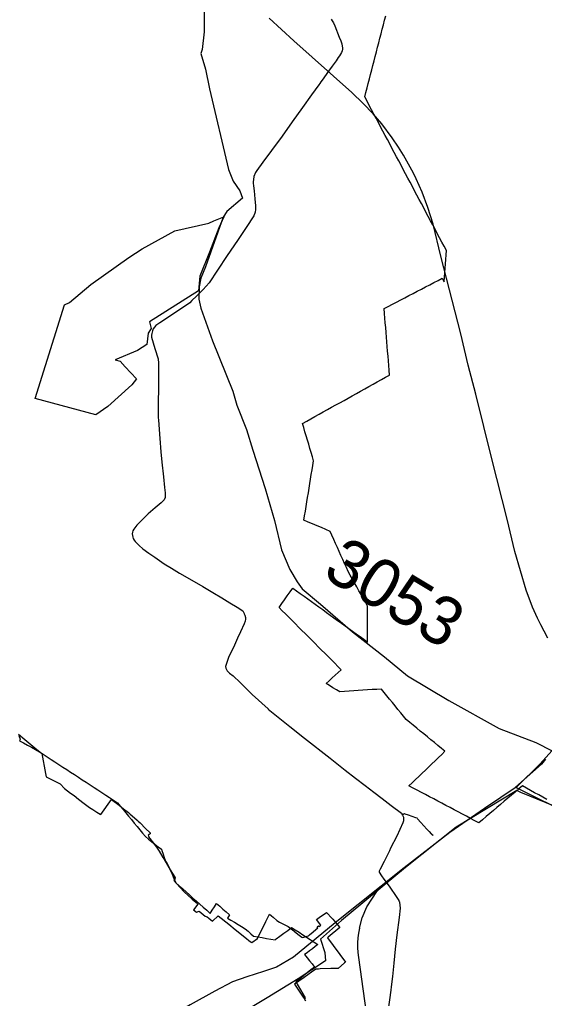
# Model space of a CAD drawing. Extents: x -789162 to -606354, y -1062736 to -945481.
# Drawn here: x -723737 to -722652, y -987074 to -985051 of the extents above; entities that cross this region are included whole.
import ezdxf

# ---------------------------------------------------------------- set-up
doc = ezdxf.new("R2010")
doc.units = 0
for name, color, linetype in [('_SIRSI VZTAHY CHKO HRANICE', 7, 'Continuous'), ('_SIRSI VZTAHY_CYKLOTRASY MISTNI S', 7, 'Continuous'), ('_SIRSI VZTAHY_CYKLOTRASY MISTNI_POPIS', 7, 'Continuous'), ('_SIRSI VZTAHY_NATURA_EVL', 7, 'Continuous'), ('_SIRSI VZTAHY_OP vodnich zdroju II stupne', 7, 'Continuous'), ('_SIRSI VZTAHY_SILNICE III TRIDY_NAVRH', 7, 'Continuous'), ('_SIRSI VZTAHY_SILNICE III TRIDY_STAV', 7, 'Continuous'), ('_SIRSI VZTAHY_VTL PLYNOVOD', 7, 'Continuous'), ('_SIRSI VZTAHY_ZELEZNICE STAV', 7, 'Continuous')]:
    doc.layers.add(name, color=color, linetype=linetype)

msp = doc.modelspace()

# ---------------------------------------------------------------- linework, layer by layer
at = {"layer": '_SIRSI VZTAHY CHKO HRANICE'}
msp.add_lwpolyline([(-723739.4, -986527.5), (-723726.3, -986538.3), (-723713.9, -986549.2), (-723705.7, -986555.6), (-723695.8, -986564.1), (-723691.6, -986567.8), (-723683.6, -986608.7), (-723682.2, -986615.9), (-723653.4, -986630.5), (-723644.2, -986640), (-723631.9, -986649.4), (-723624.9, -986654.7), (-723615.4, -986662), (-723604, -986670.7), (-723592.6, -986679.4), (-723585.9, -986683.5), (-723577.7, -986688.6), (-723570.8, -986692.8), (-723569.2, -986693.4), (-723547.2, -986662.3), (-723531.8, -986674.6), (-723522.4, -986682.1), (-723512.1, -986689.8), (-723508.5, -986693), (-723504.7, -986696.6), (-723494.5, -986705.6), (-723492.4, -986707.5), (-723488.4, -986711.2), (-723477.2, -986722.3), (-723467.3, -986731.7), (-723467.3, -986733.3), (-723471.5, -986736.4), (-723470.2, -986738.9), (-723470.7, -986739.7), (-723460.7, -986753.2), (-723453, -986763.4), (-723448.6, -986769.6), (-723441.4, -986782.3), (-723439.5, -986785.6), (-723431.4, -986798.7), (-723426, -986807.9), (-723420.2, -986817.8), (-723415.9, -986824.7), (-723416.9, -986829.3), (-723418.4, -986830.4), (-723413.3, -986836.3), (-723398.1, -986852.6), (-723395.9, -986854.9), (-723389.5, -986860.7), (-723380.4, -986868.4), (-723369.9, -986877.6), (-723369.2, -986878.7), (-723378.1, -986890.7), (-723371.6, -986895.4), (-723366.1, -986893.3), (-723354, -986903.5), (-723349.4, -986905.5), (-723346.1, -986907.8), (-723338.5, -986914.2), (-723327.1, -986902.9), (-723305, -986920.6), (-723291.6, -986931.3), (-723271.7, -986947.2), (-723260.1, -986956.8), (-723257.5, -986958.5), (-723245.3, -986949.8), (-723228.3, -986914.6), (-723220.8, -986899.9), (-723216.8, -986903.2), (-723213.4, -986905.7), (-723205.3, -986912.6), (-723200.3, -986916.4), (-723183.9, -986924.8), (-723182.5, -986925.1), (-723170.6, -986934.3), (-723168.8, -986935.7), (-723159.4, -986943.1), (-723154.1, -986947), (-723152.8, -986947.8), (-723140.4, -986944.2), (-723138.1, -986942.7), (-723130.2, -986935.9), (-723124.7, -986931.1), (-723120.8, -986927.6), (-723121.9, -986926.1), (-723119.2, -986923.8), (-723118, -986925.3), (-723114.9, -986922.4), (-723123.9, -986910.8), (-723118, -986906.4), (-723102.6, -986896.4), (-723091.1, -986908.5), (-723090.6, -986909.3), (-723089.9, -986910.3), (-723079.4, -986922.1), (-723075.6, -986927), (-723099.5, -986947.3), (-723101, -986948.6), (-723063.5, -986999), (-723065.8, -987000.5), (-723078.9, -987011.8), (-723094.2, -987012.2), (-723115.7, -987012.9), (-723119.8, -987013.2), (-723125.1, -987013.4), (-723134, -987019.4), (-723149.1, -987030.3), (-723168.9, -987044.3), (-723151, -987071.2), (-723149.2, -987073.8), (-723146.1, -987078.5)], dxfattribs=at)
at = {"layer": '_SIRSI VZTAHY_CYKLOTRASY MISTNI S'}
for points in [[(-723356.8, -984980.7), (-723355.5, -985075.8), (-723360.2, -985112.7), (-723362.4, -985120.6), (-723353.2, -985152.9), (-723344.5, -985194), (-723305.3, -985360.4), (-723296.1, -985384.5), (-723282.3, -985404.8), (-723276.4, -985419.7), (-723308.8, -985447.5), (-723316.5, -985458.7), (-723352.9, -985561.4), (-723362.8, -985585.1), (-723366.3, -985603), (-723366.7, -985628.1), (-723362.6, -985646.9), (-723338.5, -985714.3), (-723296.4, -985818.7), (-723288.6, -985847.7), (-723268.3, -985897.7), (-723255.5, -985940.7), (-723229.5, -986019.7), (-723210.1, -986086.2), (-723195.7, -986146.8), (-723178.9, -986187.4), (-723163.8, -986212.8), (-723153.1, -986227.5), (-723115.1, -986259), (-723049.1, -986316.1), (-722982.8, -986367.6), (-722935.5, -986407.3), (-722849.8, -986458.3), (-722746.1, -986516), (-722670.4, -986544.9), (-722636.3, -986562)], [(-722650.1, -986579.3), (-722658.6, -986589.8), (-722712.4, -986637.1), (-722593, -986696.2)]]:
    msp.add_lwpolyline(points, dxfattribs=at)
at = {"layer": '_SIRSI VZTAHY_NATURA_EVL'}
for points in [[(-722647.5, -986662.7), (-722655.9, -986658), (-722664.3, -986653.3), (-722672.7, -986648.6), (-722681.1, -986643.9), (-722689.5, -986639.2), (-722697.9, -986634.5), (-722705.4, -986640.8), (-722712.9, -986647.2), (-722720.4, -986653.6), (-722728, -986659.9), (-722735.5, -986666.3), (-722743, -986672.7), (-722750.5, -986679), (-722758, -986685.4), (-722765.5, -986691.8), (-722773, -986698.1), (-722780.6, -986704.5), (-722788.1, -986710.9), (-722796.6, -986706.4), (-722805, -986701.9), (-722813.5, -986697.4), (-722822, -986692.9), (-722830.5, -986688.4), (-722839, -986683.9), (-722847.5, -986679.4), (-722856, -986674.9), (-722864.5, -986670.4), (-722872.9, -986665.9), (-722881.4, -986661.4), (-722889.9, -986656.9), (-722898.4, -986652.4), (-722906.9, -986648), (-722915.4, -986643.5), (-722923.9, -986639), (-722932.4, -986634.5), (-722925.6, -986628), (-722918.8, -986621.5), (-722912.1, -986615), (-722905.3, -986608.5), (-722898.6, -986602), (-722891.8, -986595.5), (-722885, -986589), (-722878.3, -986582.5), (-722871.5, -986576), (-722864.8, -986569.5), (-722858, -986563), (-722865.3, -986557), (-722872.6, -986551), (-722879.9, -986545.1), (-722887.1, -986539.1), (-722894.4, -986533.1), (-722901.7, -986527.1), (-722909, -986521.1), (-722916.2, -986515.2), (-722923.5, -986509.2), (-722930.8, -986503.2), (-722938.1, -986497.2), (-722943.8, -986490.2), (-722949.5, -986483.2), (-722955.2, -986476.3), (-722961, -986469.3), (-722966.7, -986462.3), (-722972.4, -986455.3), (-722978.1, -986448.3), (-722983.8, -986441.3), (-722989.5, -986434.3), (-722999.1, -986435), (-723008.6, -986435.6), (-723018.1, -986436.2), (-723027.7, -986436.9), (-723037.2, -986437.5), (-723046.7, -986438.1), (-723056.3, -986438.8), (-723065.8, -986439.4), (-723075.3, -986440), (-723082.5, -986435.7), (-723089.6, -986431.5), (-723096.8, -986427.2), (-723103.9, -986422.9), (-723097.6, -986417.2), (-723091.3, -986411.4), (-723085, -986405.7), (-723078.8, -986400), (-723072.5, -986394.3), (-723079.2, -986387.5), (-723086, -986380.7), (-723092.8, -986374), (-723099.6, -986367.2), (-723106.3, -986360.4), (-723113.1, -986353.7), (-723119.9, -986346.9), (-723126.6, -986340.1), (-723133.4, -986333.3), (-723140.2, -986326.6), (-723147, -986319.8), (-723153.7, -986313), (-723160.5, -986306.3), (-723167.3, -986299.5), (-723174, -986292.7), (-723180.8, -986285.9), (-723187.6, -986279.2), (-723194.4, -986272.4), (-723201.1, -986265.6), (-723195.4, -986257.6), (-723189.7, -986249.6), (-723184, -986241.6), (-723178.3, -986233.6), (-723172.5, -986225.6), (-723164.8, -986231.2), (-723157.1, -986236.7), (-723149.4, -986242.3), (-723141.7, -986247.9), (-723133.9, -986253.5), (-723126.2, -986259), (-723118.5, -986264.6), (-723110.8, -986270.2), (-723103.1, -986275.8), (-723095.3, -986281.3), (-723087.6, -986286.9), (-723079.9, -986292.5), (-723072.2, -986298.1), (-723064.5, -986303.6), (-723056.7, -986309.2), (-723049, -986314.8), (-723041.3, -986320.4), (-723033.6, -986326), (-723025.9, -986331.5), (-723018.1, -986337.1), (-723018.1, -986327.8), (-723018.1, -986318.5), (-723018.1, -986309.2), (-723018.1, -986299.9), (-723018.1, -986290.6), (-723018.1, -986281.3), (-723018.1, -986272.1), (-723018.1, -986262.8), (-723022.6, -986254.8), (-723027, -986246.9), (-723031.5, -986238.9), (-723035.9, -986231), (-723040.4, -986223), (-723044.8, -986215.1), (-723049.3, -986207.2), (-723053.7, -986199.2), (-723058.2, -986191.3), (-723061.9, -986183), (-723065.6, -986174.7), (-723069.3, -986166.4), (-723073, -986158.1), (-723076.8, -986149.8), (-723080.5, -986141.5), (-723084.2, -986133.2), (-723087.9, -986124.9), (-723091.6, -986116.6), (-723095.3, -986108.4), (-723104.4, -986104.5), (-723113.4, -986100.7), (-723122.5, -986096.9), (-723131.6, -986093.1), (-723140.6, -986089.3), (-723149.7, -986085.5), (-723148.1, -986076), (-723146.6, -986066.6), (-723145, -986057.1), (-723143.5, -986047.7), (-723142, -986038.2), (-723140.4, -986028.7), (-723138.9, -986019.3), (-723137.3, -986009.8), (-723135.8, -986000.4), (-723134.3, -985990.9), (-723132.7, -985981.4), (-723131.2, -985972), (-723129.7, -985962.5), (-723132.2, -985954), (-723134.7, -985945.4), (-723137.3, -985936.8), (-723139.8, -985928.2), (-723142.4, -985919.6), (-723144.9, -985911.1), (-723147.4, -985902.5), (-723150, -985893.9), (-723152.5, -985885.3), (-723143.9, -985880.6), (-723135.4, -985875.8), (-723126.8, -985871), (-723118.2, -985866.3), (-723109.6, -985861.5), (-723101.1, -985856.7), (-723092.5, -985852), (-723083.9, -985847.2), (-723075.3, -985842.4), (-723066.7, -985837.7), (-723058.2, -985832.9), (-723049.6, -985828.1), (-723041, -985823.4), (-723032.4, -985818.6), (-723023.9, -985813.8), (-723015.3, -985809.1), (-723006.7, -985804.3), (-722998.1, -985799.6), (-722989.5, -985794.8), (-722981, -985790), (-722972.4, -985785.3), (-722973.2, -985775.5), (-722974, -985765.6), (-722974.8, -985755.8), (-722975.7, -985746), (-722976.5, -985736.2), (-722977.3, -985726.4), (-722978.1, -985716.6), (-722978.9, -985706.8), (-722979.7, -985697), (-722980.6, -985687.2), (-722981.4, -985677.4), (-722982.2, -985667.6), (-722983, -985657.8), (-722983.8, -985648), (-722975.2, -985643.5), (-722966.7, -985639), (-722958.1, -985634.5), (-722949.5, -985630), (-722940.9, -985625.5), (-722932.4, -985621), (-722923.8, -985616.6), (-722915.2, -985612.1), (-722906.6, -985607.6), (-722898, -985603.1), (-722889.5, -985598.6), (-722880.9, -985594.1), (-722872.3, -985589.6), (-722863.7, -985585.1), (-722859.4, -985592.3), (-722858.8, -985583.1), (-722858.2, -985573.9), (-722857.6, -985564.7), (-722857, -985555.5), (-722856.4, -985546.3), (-722855.8, -985537.1), (-722855.2, -985527.9), (-722859.8, -985519.1), (-722864.5, -985510.3), (-722869.2, -985501.5), (-722873.9, -985492.7), (-722878.6, -985483.8), (-722883.3, -985475), (-722888, -985466.2), (-722892.6, -985457.4), (-722897.3, -985448.6), (-722902, -985439.8), (-722906.7, -985430.9), (-722911.4, -985422.1), (-722916.1, -985413.3), (-722920.8, -985404.5), (-722925.4, -985395.7), (-722930.1, -985386.9), (-722934.8, -985378), (-722939.5, -985369.2), (-722944.2, -985360.4), (-722948.9, -985351.6), (-722953.6, -985342.8), (-722958.3, -985334), (-722962.9, -985325.1), (-722967.6, -985316.3), (-722972.3, -985307.5), (-722977, -985298.7), (-722981.7, -985289.9), (-722986.4, -985281.1), (-722991.1, -985272.2), (-722995.7, -985263.4), (-723000.4, -985254.6), (-723005.1, -985245.8), (-723009.8, -985237), (-723014.5, -985228.2), (-723019.2, -985219.3), (-723023.9, -985210.5), (-723021.4, -985201.2), (-723019, -985191.9), (-723016.6, -985182.5), (-723014.2, -985173.2), (-723011.8, -985163.9), (-723009.4, -985154.6), (-723007, -985145.2), (-723004.6, -985135.9), (-723002.2, -985126.6), (-722999.8, -985117.2), (-722997.4, -985107.9), (-722995, -985098.6), (-722992.6, -985089.2), (-722990.1, -985079.9), (-722987.7, -985070.6), (-722985.3, -985061.2), (-722982.9, -985051.9), (-722980.5, -985042.6)], [(-723738.9, -986530.1), (-723736.1, -986538.1), (-723737.9, -986541.1), (-723729.6, -986545.6), (-723721.3, -986550.2), (-723713.1, -986554.8), (-723704.8, -986559.3), (-723696.5, -986563.9), (-723688.4, -986569.1), (-723680.4, -986574.4), (-723672.3, -986579.7), (-723664.2, -986584.9), (-723656.1, -986590.2), (-723648.1, -986595.5), (-723640, -986600.8), (-723631.9, -986606), (-723623.9, -986611.3), (-723615.8, -986616.6), (-723607.7, -986621.8), (-723599.6, -986627.1), (-723591.6, -986632.4), (-723583.5, -986637.6), (-723575.4, -986642.9), (-723567.4, -986648.2), (-723559.3, -986653.4), (-723551.2, -986658.7), (-723543.1, -986664), (-723535.1, -986669.2), (-723529.3, -986676.3), (-723523.5, -986683.3), (-723517.7, -986690.3), (-723512, -986697.3), (-723506.2, -986704.3), (-723500.4, -986711.3), (-723494.6, -986718.3), (-723488.9, -986725.4), (-723483.1, -986732.4), (-723477.3, -986739.4), (-723470.7, -986744.6), (-723464.1, -986749.9), (-723457.5, -986755.1), (-723450.9, -986760.4), (-723444.2, -986765.6), (-723443.2, -986768.1), (-723440.7, -986775.5), (-723438.3, -986782.8), (-723435.8, -986790.1), (-723432.9, -986794.4), (-723429.9, -986798.8), (-723426, -986807.7), (-723422.2, -986816.7), (-723418.3, -986825.6), (-723414.4, -986834.6), (-723407.3, -986840.9), (-723400.2, -986847.3), (-723393.1, -986853.6), (-723386.1, -986860), (-723379, -986866.3), (-723371.9, -986872.7), (-723364.8, -986879), (-723357.7, -986885.4), (-723350.6, -986891.7), (-723343.6, -986898.1), (-723339.1, -986891.2), (-723334.7, -986884.3), (-723330.3, -986877.4), (-723323.7, -986883.2), (-723317, -986889.1), (-723310.4, -986895), (-723303.8, -986900.9), (-723307.9, -986907.7), (-723300.5, -986912.1), (-723293.1, -986916.5), (-723285.8, -986921), (-723278.4, -986925.4), (-723271, -986929.8), (-723265.2, -986935), (-723259.4, -986940.1), (-723253.6, -986945.2), (-723244.7, -986946.7), (-723235.9, -986948.2), (-723227, -986949.7), (-723218.2, -986951.1), (-723209.3, -986952.6), (-723207.6, -986951.5), (-723207.1, -986950.9), (-723199.1, -986945), (-723191.2, -986939.1), (-723183.2, -986933.1), (-723175.2, -986927.2), (-723167.5, -986932.2), (-723159.7, -986937.2), (-723152, -986942.2), (-723144.2, -986947.2), (-723136.5, -986952.2), (-723128.7, -986957.2), (-723120.9, -986962.2), (-723126.6, -986966.6), (-723132.2, -986971.1), (-723137.9, -986975.6), (-723143.1, -986979.4), (-723148.4, -986983.3), (-723143.2, -986989.7), (-723138, -986996.1), (-723132.8, -987002.5), (-723127.6, -987008.9), (-723135.2, -987015), (-723142.9, -987021.1), (-723150.6, -987027.2), (-723158.3, -987033.3), (-723166, -987039.4), (-723161.3, -987047.7), (-723156.6, -987056.1), (-723151.9, -987064.4), (-723147.2, -987072.8), (-723148.2, -987074.8)]]:
    msp.add_lwpolyline(points, dxfattribs=at)
at = {"layer": '_SIRSI VZTAHY_OP vodnich zdroju II stupne'}
msp.add_lwpolyline([(-723634.4, -985635.1), (-723589.9, -985598.1), (-723511.8, -985542.6), (-723483.9, -985524.7), (-723416.7, -985487.5), (-723346, -985471.6), (-723335.8, -985466.4), (-723315.5, -985458.2), (-723325.5, -985481), (-723344.7, -985531.3), (-723364.9, -985581.1), (-723367.6, -985611.4), (-723469.1, -985675.3), (-723465.6, -985689.2), (-723471.9, -985698.6), (-723474.6, -985722.1), (-723493.3, -985734.7), (-723540.1, -985753.8), (-723529.5, -985756.6), (-723518.9, -985768.3), (-723495.4, -985793), (-723505.6, -985805.2), (-723554.9, -985850.2), (-723579.6, -985867.3), (-723705.1, -985834.1), (-723644.2, -985640.5)], close=True, dxfattribs=at)
msp.add_lwpolyline([(-722581.1, -986697.1), (-722701.4, -986648.1), (-722709.4, -986644.2), (-722835.1, -986719.6), (-722939.6, -986802.9), (-723071.9, -986912.7), (-723115.5, -986951.1), (-723106.3, -986978.9), (-723104.9, -986996.1), (-723161.8, -987033.1), (-723225.3, -987072.8), (-723263.7, -987095.3)], dxfattribs=at)
at = {"layer": '_SIRSI VZTAHY_SILNICE III TRIDY_NAVRH'}
for points in [[(-723034.9, -986928.7), (-723029.1, -986907.3), (-723019.5, -986884.7), (-722998.8, -986853), (-722985.3, -986837.8)], [(-723034.9, -986928.7), (-723036.7, -986938.6), (-723037.9, -986948.6), (-723038.6, -986958.7), (-723038.6, -986968.8), (-723038.1, -986978.8), (-723037, -986988.9), (-722989.9, -987327.3)]]:
    msp.add_lwpolyline(points, dxfattribs=at)
at = {"layer": '_SIRSI VZTAHY_SILNICE III TRIDY_STAV'}
msp.add_lwpolyline([(-722637.4, -986561.8), (-722661.1, -986589.1), (-722708.9, -986635.9), (-722776.2, -986681.3), (-722847.7, -986730.8), (-722942.6, -986803.6), (-723084.9, -986917.3), (-723171.2, -986988.8), (-723206.1, -987009.4), (-723233.4, -987018), (-723267.3, -987029), (-723297.3, -987039.3), (-723333.7, -987058.5), (-723384.6, -987086.8), (-723434.1, -987116.2), (-723468.3, -987132.7), (-723496.5, -987144), (-723615.3, -987176.7)], dxfattribs=at)
at = {"layer": '_SIRSI VZTAHY_VTL PLYNOVOD'}
for points in [[(-723093.6, -985050), (-723091.2, -985053), (-723088.4, -985057.3), (-723085.7, -985063.2), (-723076.6, -985086.6), (-723073.5, -985094.5), (-723071.2, -985100.6), (-723070, -985109.8), (-723070.2, -985111.7), (-723070.7, -985114.8), (-723072.1, -985118.5), (-723074, -985122.1), (-723075.9, -985125.3), (-723078.6, -985128.9), (-723082.9, -985135.6), (-723091.4, -985146.9), (-723091.4, -985147), (-723100.7, -985159.6), (-723110, -985173.3), (-723114.6, -985179.3), (-723117, -985182.5), (-723119.1, -985185.3), (-723133.8, -985205.8), (-723152.6, -985232.2), (-723174.1, -985262.2), (-723194.9, -985291.2), (-723216.6, -985321.3), (-723234.6, -985345.3), (-723247.2, -985362.4), (-723249.9, -985366.6), (-723252.9, -985374.9), (-723252.9, -985374.9), (-723254.4, -985386.8), (-723254.2, -985389), (-723253.7, -985394), (-723252.7, -985404.3), (-723251.1, -985421), (-723249.7, -985435.2), (-723249.7, -985441.1), (-723249.8, -985443.3), (-723250.7, -985448.8), (-723253.3, -985455.9), (-723254.4, -985458.4), (-723257.1, -985462.7), (-723264.7, -985474.1), (-723287.2, -985507), (-723308.3, -985538.2), (-723328.6, -985568.7), (-723345.2, -985594.7), (-723358, -985608.6), (-723363, -985613.2), (-723371.6, -985622), (-723381.1, -985631.5), (-723381.1, -985631.5), (-723385.5, -985635.9), (-723408.9, -985651.8), (-723447.4, -985677.2), (-723455.6, -985683.1), (-723458.6, -985686.4), (-723461, -985690), (-723462.7, -985693.7), (-723462.7, -985693.8), (-723464.2, -985699.4), (-723464.5, -985702.9), (-723464.4, -985707.1), (-723458, -985730.1), (-723451.2, -985751.5), (-723450.7, -985754.5), (-723450.4, -985758.1), (-723450.3, -985760.5), (-723450.3, -985765.8), (-723450.3, -985778.8), (-723450.5, -985810.1), (-723451.1, -985844.1), (-723451, -985862.6), (-723450.9, -985872.8), (-723450.9, -985872.8), (-723450.3, -985878.8), (-723447.3, -985916.3), (-723445.1, -985943.8), (-723443.6, -985965.6), (-723439.9, -985995.9), (-723437.5, -986017.7), (-723436.7, -986029), (-723436.7, -986038.7), (-723436.7, -986038.7), (-723438.4, -986043.1), (-723438.4, -986043.2), (-723444.7, -986049.3), (-723457.3, -986059.9), (-723471.9, -986072.5), (-723484.4, -986085.1), (-723494.8, -986095.9), (-723501.3, -986103.9), (-723503, -986107), (-723504, -986110.2), (-723504.5, -986113.7), (-723503.3, -986120.5), (-723503.3, -986120.5), (-723502.4, -986123.1), (-723500.2, -986126.9), (-723498.2, -986129.4), (-723490.3, -986137.4), (-723482.7, -986144.4), (-723470.4, -986153.4), (-723457.9, -986162), (-723438.3, -986175.6), (-723438.3, -986175.6), (-723438.2, -986175.6), (-723423.2, -986184.8), (-723406.7, -986194.6), (-723381, -986209.6), (-723358.8, -986222.6), (-723358.7, -986222.6), (-723338.1, -986234.7), (-723319.4, -986245.8), (-723302.8, -986255.8), (-723287.6, -986264.9), (-723276.1, -986272.9), (-723274.3, -986275.5), (-723272.9, -986278.4), (-723272.8, -986278.7), (-723271.8, -986281.7), (-723270.6, -986286.4), (-723270.4, -986289.6), (-723271, -986293.7), (-723273.2, -986299.4), (-723280.7, -986316), (-723286.9, -986329.3), (-723293.4, -986343.4), (-723305.2, -986368.8), (-723311.4, -986387.8), (-723311, -986391.3), (-723311, -986391.3), (-723308.6, -986396.5), (-723303.3, -986401.7), (-723295.9, -986407.3), (-723281.2, -986421), (-723256.7, -986445.9), (-723223.5, -986475.5), (-723223.3, -986475.7), (-723199.2, -986495), (-723178.5, -986511.8), (-723148.1, -986535.7), (-723095.2, -986577.4), (-723064.2, -986601.7), (-723043.1, -986618.2), (-723023.3, -986633.6), (-723005.1, -986647.8), (-722988.2, -986660.8), (-722969.6, -986675), (-722947.7, -986691.2), (-722947.4, -986692), (-722947.2, -986692.7), (-722947.2, -986692.7), (-722946.7, -986693.6)], [(-722946.7, -986693.6), (-722946.7, -986693.6), (-722946.2, -986694.4), (-722946.1, -986694.7), (-722944.1, -986699.3), (-722944.1, -986699.3), (-722943.8, -986702), (-722944.1, -986707), (-722945.1, -986711.2), (-722957.7, -986738.5), (-722970.4, -986763.5), (-722972.8, -986768.6), (-722972.8, -986768.6), (-722983.7, -986790.9), (-722992.1, -986806.9), (-722994.2, -986811), (-722994.2, -986811.1), (-722994.4, -986813), (-722989, -986820.3), (-722989, -986820.3), (-722984.1, -986827.5), (-722977.6, -986836.1), (-722972.3, -986843.9), (-722972.3, -986844), (-722958.8, -986862.8), (-722955.9, -986867), (-722954.8, -986869.1), (-722953.6, -986871.7), (-722953.5, -986871.8), (-722953, -986872.9), (-722952.3, -986874.7), (-722951, -986887.3), (-722953, -986906.8), (-722957.6, -986942.5), (-722961, -986972.1), (-722963.9, -987001.2), (-722966.8, -987028.3), (-722969.1, -987049.6), (-722970.1, -987057), (-722983.1, -987151.2)], [(-722946.7, -986693.6), (-722946.6, -986693.5), (-722946.5, -986693.4), (-722946.4, -986693.4), (-722946.2, -986693.3)], [(-722946.2, -986693.3), (-722946.4, -986692.9), (-722946.3, -986692.8), (-722945.8, -986692.6), (-722945.6, -986692.5), (-722945.4, -986692.9)], [(-722946.2, -986693.3), (-722945.8, -986693.1), (-722945.4, -986692.9)], [(-722945.4, -986692.9), (-722945.2, -986692.8), (-722945.1, -986692.8), (-722945, -986692.7), (-722944.7, -986692.5), (-722944.4, -986693), (-722944, -986692.8), (-722942.8, -986692.2), (-722942, -986691.8), (-722941.3, -986692.1), (-722934.3, -986694.6), (-722918.8, -986699.9), (-722916.5, -986700.6), (-722915.5, -986701.4), (-722914.7, -986702.3), (-722907.8, -986710), (-722895.2, -986723.7), (-722890.4, -986729), (-722886.3, -986733.5), (-722885.3, -986734.6), (-722884.7, -986735.3), (-722884.6, -986735.5)], [(-722884.6, -986735.5), (-722884.2, -986735.1), (-722884, -986735.3), (-722883.8, -986735.5), (-722883.5, -986735.9), (-722883.9, -986736.3)], [(-722883.9, -986736.3), (-722884, -986736.1), (-722884.2, -986735.9), (-722884.6, -986735.5)], [(-722883.9, -986736.3), (-722883.7, -986736.4), (-722883.4, -986736.8), (-722882.9, -986736.4), (-722882.9, -986736.4), (-722882.9, -986736.3), (-722882.4, -986735.9)]]:
    msp.add_lwpolyline(points, dxfattribs=at)
at = {"layer": '_SIRSI VZTAHY_ZELEZNICE STAV'}
msp.add_lwpolyline([(-722645.1, -986329.4), (-722653.1, -986314.7), (-722659.7, -986301.6), (-722666.6, -986287.5), (-722677, -986264.8), (-722690.1, -986229.9), (-722713.3, -986149.7), (-722729.5, -986083.1), (-722761.1, -985958.4), (-722794.3, -985824.5), (-722809.9, -985764.7), (-722825.3, -985700.3), (-722866.4, -985539.3), (-722882.3, -985473.2), (-722893.4, -985439), (-722905.1, -985407.3), (-722917.7, -985379.4), (-722923, -985368.3), (-722943.8, -985330.9), (-722954.2, -985314), (-722967.2, -985294.9), (-722988.8, -985266), (-723006.6, -985245.1), (-723026.9, -985223.7), (-723050.5, -985201), (-723170.2, -985094.4), (-723221.5, -985047.8)], dxfattribs=at)

# ---------------------------------------------------------------- texts
at = {"layer": '_SIRSI VZTAHY_CYKLOTRASY MISTNI_POPIS'}
msp.add_text('3053', height=100, rotation=329.0189, dxfattribs=at).set_placement((-723114.1, -986200.6))

doc.saveas('drawing.dxf')
